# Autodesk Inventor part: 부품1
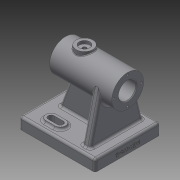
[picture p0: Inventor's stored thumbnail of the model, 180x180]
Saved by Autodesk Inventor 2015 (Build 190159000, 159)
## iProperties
Created: 2022-06
Part Number: 부품1
Material: 일반
Document SubType Name: Modeling
Designer: 10462
Density: 1 g/cm^3
Appearance: 기본값
Mass: 234.742 g
Surface Area: 513.531 cm^2
Volume: 234.742 cm^3
Author: 10462
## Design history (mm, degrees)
sketch "스케치1"
  geometry: L1 (-50, -43)-(50, -43); L2 (50, -43)-(50, 43); L3 (50, 43)-(-50, 43); L4 (-50, 43)-(-50, -43); L5 (-50, -43)-(50, 43); L6 (50, -43)-(-50, 43); 1 further point
  constraints: 12 end point, 2 midpoint, 2 parallel, 1 horizontal, 1 perpendicular
  dimensions: "d0" = 86 distance of L1.end L2.end; "d1" = 100 distance of L2.end L3.end
extrude "돌출1" new body sketch "스케치1" distance "d2" = 15; taper "d3" = 0 deg
sketch "스케치2"
  geometry: L1 (50, -43)-(50, 43) reference; L2 (-50, 43)-(-50, -43) reference; L3 (-35, -5)-(35, -5); L4 (35, -5)-(35, 5); L5 (35, 5)-(-35, 5); L6 (-35, 5)-(-35, -5); L7 (-35, -5)-(35, 5); L8 (35, -5)-(-35, 5); 6 further points
  constraints: 12 end point, 4 midpoint, 2 parallel, 1 coincident, 1 horizontal, 1 horizontal alignment, 1 perpendicular
  dimensions: "d5" = 10 distance between parallel lines of L3 L5; "d7" = 15 distance between parallel lines of L2 L6; "d9" = 15 distance between parallel lines of L1 L4
extrude "돌출2" join sketch "스케치2" distance "d10" = 57; taper "d11" = 0 deg
sketch "스케치3"
  geometry: L1 (0, 10)-(-57, 10) reference; L2 (-57, 0)-(-57, 10) reference; L3 (0, 0)-(-57, 0) reference; L4 (0, 48)-(0, -38) reference; L5 (0, -30)-(-61.814, -15.441); L6 (0, 40)-(-61.814, 25.441); L7 (0, -38)-(0, 48) reference; L8 (15, -38)-(0, -38) reference; L9 (15, 48)-(0, 48) reference; A1 r 21 centre (-57, 5) between (-61.814, -15.441) and (-61.814, 25.441); 1 further point
  constraints: 4 end point, 2 point on circle, 2 point on line, 2 tangent, 1 centre point, 1 midpoint
  dimensions: "d12" = 42 diameter of A1; "d13" = 8 distance from line of L5.start L8; "d14" = 8 distance from line of L9 L6.start
extrude "돌출3" join sketch "스케치3" distance "d15" = 10; taper "d16" = 0 deg
feature "면 기울기1" dims angle "d20" = 20 deg
sketch "스케치4"
  geometry: C1 r 21 at (-72, 43); A1 r 21 centre (-72, 43) between (-51.604, 48) and (-76.814, 63.441) reference; 1 further point
  constraints: 1 centre point, 1 coincident
  dimensions: "d17" = 42 diameter of C1
extrude "돌출4" join sketch "스케치4" distance "d18" = 82; taper "d19" = 0 deg
hole "구멍1" diameter "d23" = 23; stored, may be unused: countersink angle "d27" = 90 deg, drill point angle "d29" = 0 deg; dims "d21" = 10, "d22" = 10, "d24" = 6, "d25" = 4, "d26" = 2, "d28" = 20
hole "구멍2" diameter "d32" = 29; stored, may be unused: countersink angle "d36" = 90 deg, drill point angle "d38" = 0 deg; dims "d33" = 6, "d34" = 4, "d35" = 2, "d37" = 20, "d44" = 10, "d45" = 10
node "작업 평면1"
sketch "스케치6"
  geometry: L1 (32, -21)-(32, 21) reference; C1 r 11 at (7, 0); 1 further point
  constraints: 1 centre point, 1 horizontal alignment
  dimensions: "d40" = 22 diameter of C1; "d41" = 25 distance from line of C1.centre L1
extrude "돌출5" join sketch "스케치6" stored distance "d42" = 82; taper "d43" = 0 deg
hole "구멍3" diameter "d48" = 14; stored, may be unused: countersink angle "d52" = 90 deg, drill point angle "d54" = 0 deg; dims "d46" = 10, "d47" = 10, "d49" = 6, "d50" = 4, "d51" = 2, "d53" = 4
hole "구멍4" diameter "d57" = 4.917; stored, may be unused: countersink angle "d61" = 90 deg, drill point angle "d63" = 0 deg; dims "d55" = 10, "d56" = 10, "d58" = 12, "d59" = 4, "d60" = 2, "d62" = 17.1
sketch "스케치7"
  geometry: L1 (-50, -43)-(50, -43) reference; L2 (-50, 43)-(-50, -43) reference; L3 (-24, -27)-(-12, -27); L4 (-24, -34)-(-12, -34); L5 (-12, -20)-(-24, -20); A1 r 7 centre (-24, -27) between (-24, -20) and (-24, -34); A2 r 7 centre (-12, -27) between (-12, -34) and (-12, -20); 2 further points
  constraints: 8 end point, 4 point on circle, 4 tangent, 2 centre point, 1 horizontal, 1 midpoint, 1 parallel
  dimensions: "d64" = 12 distance of L3.start L3.end; "d65" = 26 distance from line of L5.end L2; "d66" = 16 distance between parallel lines of L3 L1; "d67" = 14 distance between parallel lines of L4 L5
extrude "돌출6" join sketch "스케치7" distance "d68" = 3; taper "d69" = 0 deg
sketch "스케치8"
  geometry: L1 (-24, -34)-(-12, -34) reference; L2 (-12, -20)-(-24, -20) reference; L3 (-24, -23)-(-12, -23); L4 (-12, -31)-(-24, -31); A1 r 7 centre (-12, -27) between (-12, -34) and (-12, -20) reference; A2 r 7 centre (-24, -27) between (-24, -20) and (-24, -34) reference; A3 r 4 centre (-12, -27) between (-12, -31) and (-12, -23); A4 r 4 centre (-24, -27) between (-24, -23) and (-24, -31); 1 further point
  constraints: 4 end point, 4 point on circle, 2 centre point, 3 other
  dimensions: "d70" = 8 distance between parallel lines of L4 L3
extrude "돌출7" cut sketch "스케치8" stored distance "d71" = 3; taper "d72" = 0 deg
fillet "모깎기1" dims "d73" = 3
fillet "모깎기2" dims "d74" = 3
sketch "스케치9"
  geometry: C1 r 11.5 at (0, 0) reference; 2 further points
  constraints: 1 horizontal alignment
  dimensions: "d75" = 18 distance of C1.centre point (-18, 0)
hole "구멍5" sketch "스케치9" at (-18, 0) diameter "d76" = 2.459; stored, may be unused: countersink angle "d80" = 90 deg, drill point angle "d82" = 118 deg; dims "d77" = 8, "d78" = 4, "d79" = 2, "d81" = 10
node "작업 평면2"
fillet "모깎기3" dims "d86" = 1
chamfer "모따기1" distance "d87" = 1; stored, may be unused: second distance "d88" = 2, angle "d89" = 45 deg
fillet "모깎기4" dims "d90" = 3
fillet "모깎기5" dims "d91" = 3
fillet "모깎기6" dims "d92" = 3
fillet "모깎기7" dims "d93" = 3
fillet "모깎기8" dims "d94" = 3
sketch "스케치10"
  geometry: L1 (0, 0)-(0, 80) reference; L2 (0, 83)-(0, 80) reference; 3 further points
  constraints: 1 horizontal alignment, 1 midpoint, 1 other
  dimensions: "d98" = 6 distance from line of L2 point (-6, 40)
feature "엠보싱1" sketch "스케치10" dims "d0" = 86, "d1" = 100, "d96" = 0.5, "d97" = 0
node "솔리드1"
mirror "대칭1"
pattern_circular "원형 패턴1" dims angle "d84" = 360 deg
mirror "대칭2"
other parameters: "d39" = -96
